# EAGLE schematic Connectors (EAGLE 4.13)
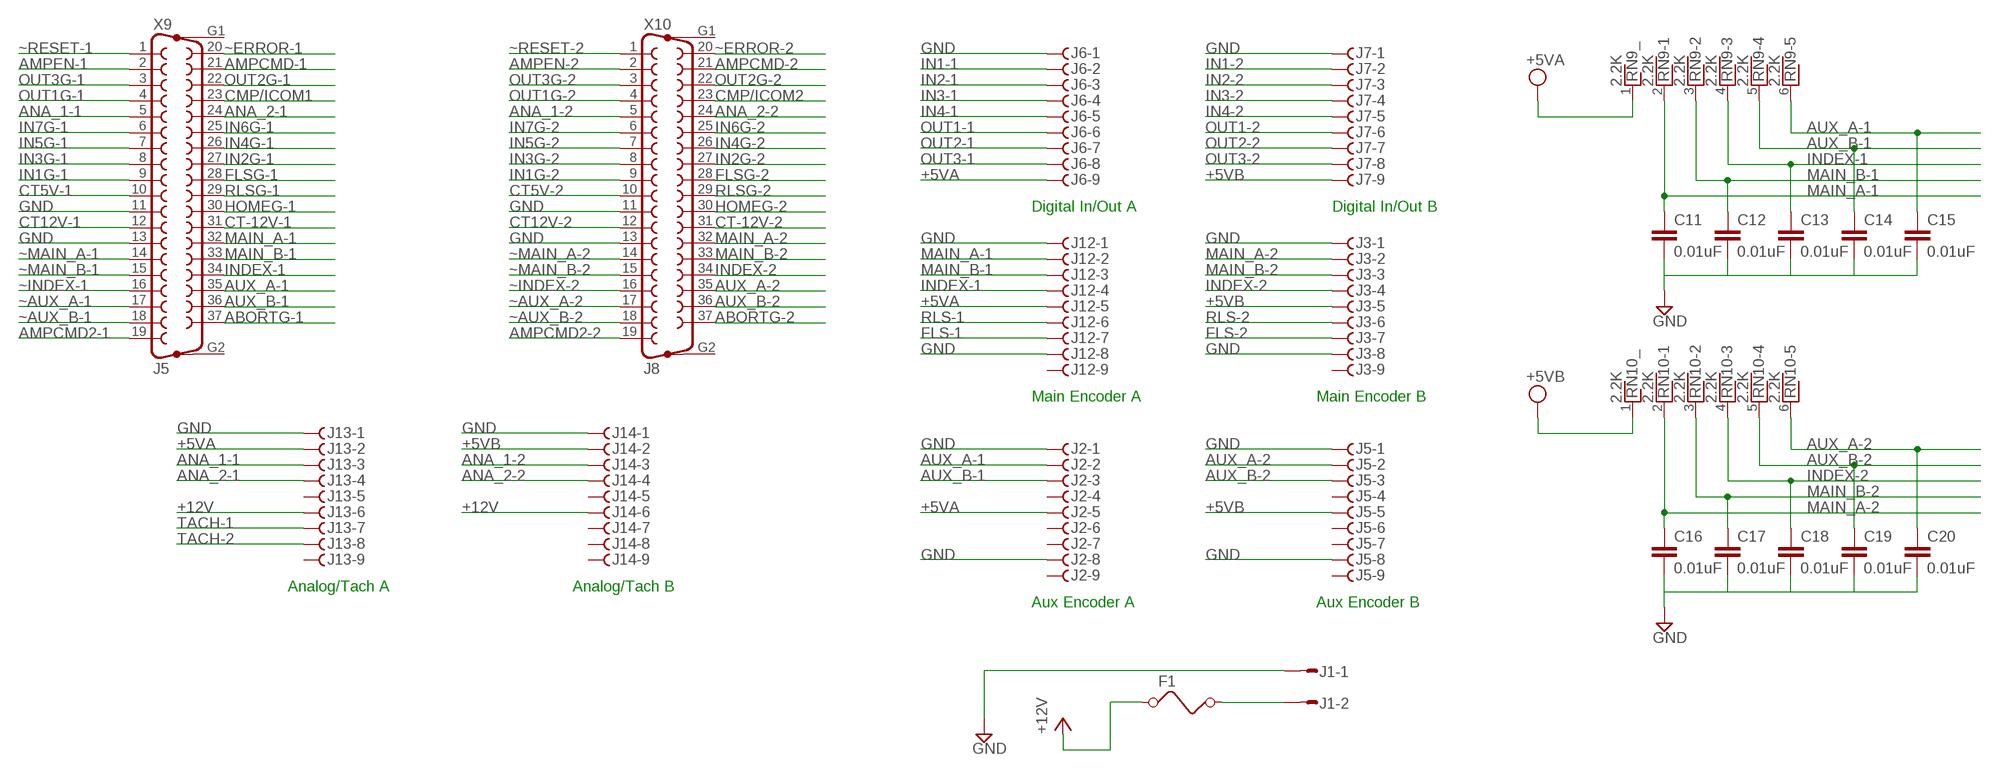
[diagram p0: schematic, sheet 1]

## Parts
C11  0.01uF  C-EU025_050-025X075  [C025_050-025X075]
C12  0.01uF  C-EU025_050-025X075  [C025_050-025X075]
C13  0.01uF  C-EU025_050-025X075  [C025_050-025X075]
C14  0.01uF  C-EU025_050-025X075  [C025_050-025X075]
C15  0.01uF  C-EU025_050-025X075  [C025_050-025X075]
C16  0.01uF  C-EU025_050-025X075  [C025_050-025X075]
C17  0.01uF  C-EU025_050-025X075  [C025_050-025X075]
C18  0.01uF  C-EU025_050-025X075  [C025_050-025X075]
C19  0.01uF  C-EU025_050-025X075  [C025_050-025X075]
C20  0.01uF  C-EU025_050-025X075  [C025_050-025X075]
F1  FUSE  [FUSE]
J1  L02P  [L02P]
J2  F09VPS  [F09VP]
J3  F09VPS  [F09VP]
J5  F09VPS  [F09VP]
J6  F09VPS  [F09VP]
J7  F09VPS  [F09VP]
J12  F09VPS  [F09VP]
J13  F09VPS  [F09VP]
J14  F09VPS  [F09VP]
RN9  2.2K  RNX5  [RN-6]
RN10  2.2K  RNX5  [RN-6]
X9  J5  F37VP  [F37VP]
X10  J8  F37VP  [F37VP]

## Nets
+5VA: J2.5 J6.9 J12.5 J13.2
+5VB: J3.5 J5.5 J7.9 J14.2
+12V: J13.6 J14.6
ABORTG-1: X9.37
ABORTG-2: X10.37
AMPCMD2-1: X9.19
AMPCMD2-2: X10.19
AMPCMD-1: X9.21
AMPCMD-2: X10.21
AMPEN-1: X9.2
AMPEN-2: X10.2
ANA_1-1: J13.3 X9.5
ANA_1-2: J14.3 X10.5
ANA_2-1: J13.4 X9.24
ANA_2-2: J14.4 X10.24
AUX_A-1: C15.1 J2.2 RN9.6 X9.35
AUX_A-2: C20.1 J5.2 RN10.6 X10.35
AUX_B-1: C14.1 J2.3 RN9.5 X9.36
AUX_B-2: C19.1 J5.3 RN10.5 X10.36
CMP/ICOM1: X9.23
CMP/ICOM2: X10.23
CT5V-1: X9.10
CT5V-2: X10.10
CT12V-1: X9.12
CT12V-2: X10.12
CT-12V-1: X9.31
CT-12V-2: X10.31
FLS-1: J12.7
FLS-2: J3.7
FLSG-1: X9.28
FLSG-2: X10.28
GND: C11.2 C12.2 C13.2 C14.2 C15.2 C16.2 C17.2 C18.2 C19.2 C20.2 J1.1 J2.1 J2.8 J3.1 J3.8 J5.1 J5.8 J6.1 J7.1 J12.1 J12.8 J13.1 J14.1 X9.11 X9.13 X10.11 X10.13
HOMEG-1: X9.30
HOMEG-2: X10.30
IN1-1: J6.2
IN1-2: J7.2
IN1G-1: X9.9
IN1G-2: X10.9
IN2-1: J6.3
IN2-2: J7.3
IN2G-1: X9.27
IN2G-2: X10.27
IN3-1: J6.4
IN3-2: J7.4
IN3G-1: X9.8
IN3G-2: X10.8
IN4-1: J6.5
IN4-2: J7.5
IN4G-1: X9.26
IN4G-2: X10.26
IN5G-1: X9.7
IN5G-2: X10.7
IN6G-1: X9.25
IN6G-2: X10.25
IN7G-1: X9.6
IN7G-2: X10.6
INDEX-1: C13.1 J12.4 RN9.4 X9.34
INDEX-2: C18.1 J3.4 RN10.4 X10.34
MAIN_A-1: C11.1 J12.2 RN9.2 X9.32
MAIN_A-2: C16.1 J3.2 RN10.2 X10.32
MAIN_B-1: C12.1 J12.3 RN9.3 X9.33
MAIN_B-2: C17.1 J3.3 RN10.3 X10.33
N$1: F1.2 J1.2
OUT1-1: J6.6
OUT1-2: J7.6
OUT1G-1: X9.4
OUT1G-2: X10.4
OUT2-1: J6.7
OUT2-2: J7.7
OUT2G-1: X9.22
OUT2G-2: X10.22
OUT3-1: J6.8
OUT3-2: J7.8
OUT3G-1: X9.3
OUT3G-2: X10.3
RLS-1: J12.6
RLS-2: J3.6
RLSG-1: X9.29
RLSG-2: X10.29
TACH-1: J13.7
TACH-2: J13.8
VCC: F1.1 RN9.1 RN10.1 ; supply symbol labelled +5VA, +5VB, +12V
~AUX_A-1: X9.17
~AUX_A-2: X10.17
~AUX_B-1: X9.18
~AUX_B-2: X10.18
~ERROR-1: X9.20
~ERROR-2: X10.20
~INDEX-1: X9.16
~INDEX-2: X10.16
~MAIN_A-1: X9.14
~MAIN_A-2: X10.14
~MAIN_B-1: X9.15
~MAIN_B-2: X10.15
~RESET-1: X9.1
~RESET-2: X10.1
Unconnected: J2.4 J2.6 J2.7 J2.9 J3.9 J5.4 J5.6 J5.7 J5.9 J12.9 J13.5 J13.9 J14.5 J14.7 J14.8 J14.9 X9.G1 X9.G2 X10.G1 X10.G2

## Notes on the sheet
- Digital In/Out A | Digital In/Out B
- Main Encoder A | Main Encoder B
- Analog/Tach A | Analog/Tach B
- Aux Encoder A | Aux Encoder B

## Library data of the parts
C11-C20 = rcl:C-EU: CAPACITOR, European symbol
F1 = special:FUSE: FUSE
J1 = con-amp-mt:L02P: AMP MT CONNECTOR
J2 J3 J5-J7 J12-J14 = con-subd:F09?S: SUB-D
RN9 RN10 = resistor-net:RNX5: RESISTOR NETWORK
X9 X10 = con-subd:F37VP: SUB-D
